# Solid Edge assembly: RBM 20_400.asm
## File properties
Title: Zylinder
Author: ahadarics
Template: iso metric assembly.asm
Last saved by: ahadarics
Revision: 18
Application: Solid Edge
Username: ahadarics
Dokumentum tartalom típus: 1
Document Number: RBM 20/400
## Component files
Profilrohr.par
Kolbenstange.par
Kit.par
Mutter_1.par
Mutter_2.par
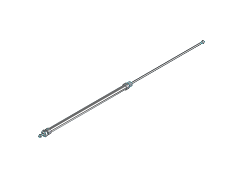
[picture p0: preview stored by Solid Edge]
